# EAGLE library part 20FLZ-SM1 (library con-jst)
CONNECTOR
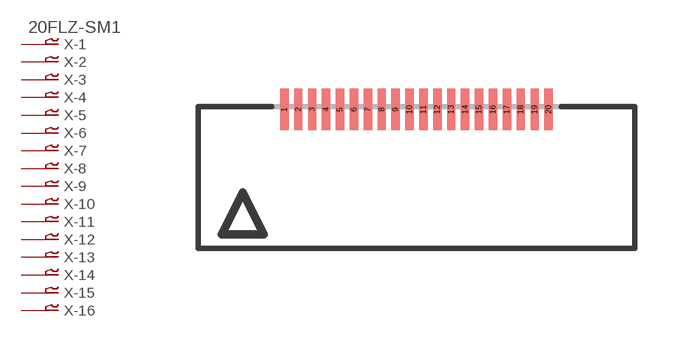
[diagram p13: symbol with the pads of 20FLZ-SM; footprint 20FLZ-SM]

Designator prefix X; gates -1=P-VN -2=P-N -3=P-N -4=P-N -5=P-N -6=P-N -7=P-N -8=P-N -9=P-N -10=P-N -11=P-N -12=P-N -13=P-N -14=P-N -15=P-N -16=P-N -17=P-N -18=P-N -19=P-N -20=P-N

## 20FLZ-SM1 (OC_FARNELL: unknown; OC_NEWARK: unknown)  [20FLZ-SM]
1  -1:1  pas
2  -2:1  pas
3  -3:1  pas
4  -4:1  pas
5  -5:1  pas
6  -6:1  pas
7  -7:1  pas
8  -8:1  pas
9  -9:1  pas
10  -10:1  pas
11  -11:1  pas
12  -12:1  pas
13  -13:1  pas
14  -14:1  pas
15  -15:1  pas
16  -16:1  pas
17  -17:1  pas
18  -18:1  pas
19  -19:1  pas
20  -20:1  pas

## Footprint 20FLZ-SM (pad centres in mm)
CONNECTOR
smd 0.3 x 1.5: 1 -4.75,2.5; 2 -4.25,2.5; 3 -3.75,2.5; 4 -3.25,2.5; 5 -2.75,2.5; 6 -2.25,2.5; 7 -1.75,2.5; 8 -1.25,2.5; 9 -0.75,2.5; 10 -0.25,2.5; 11 0.25,2.5; 12 0.75,2.5; 13 1.25,2.5; 14 1.75,2.5; 15 2.25,2.5; 16 2.75,2.5; 17 3.25,2.5; 18 3.75,2.5; 19 4.25,2.5; 20 4.75,2.5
